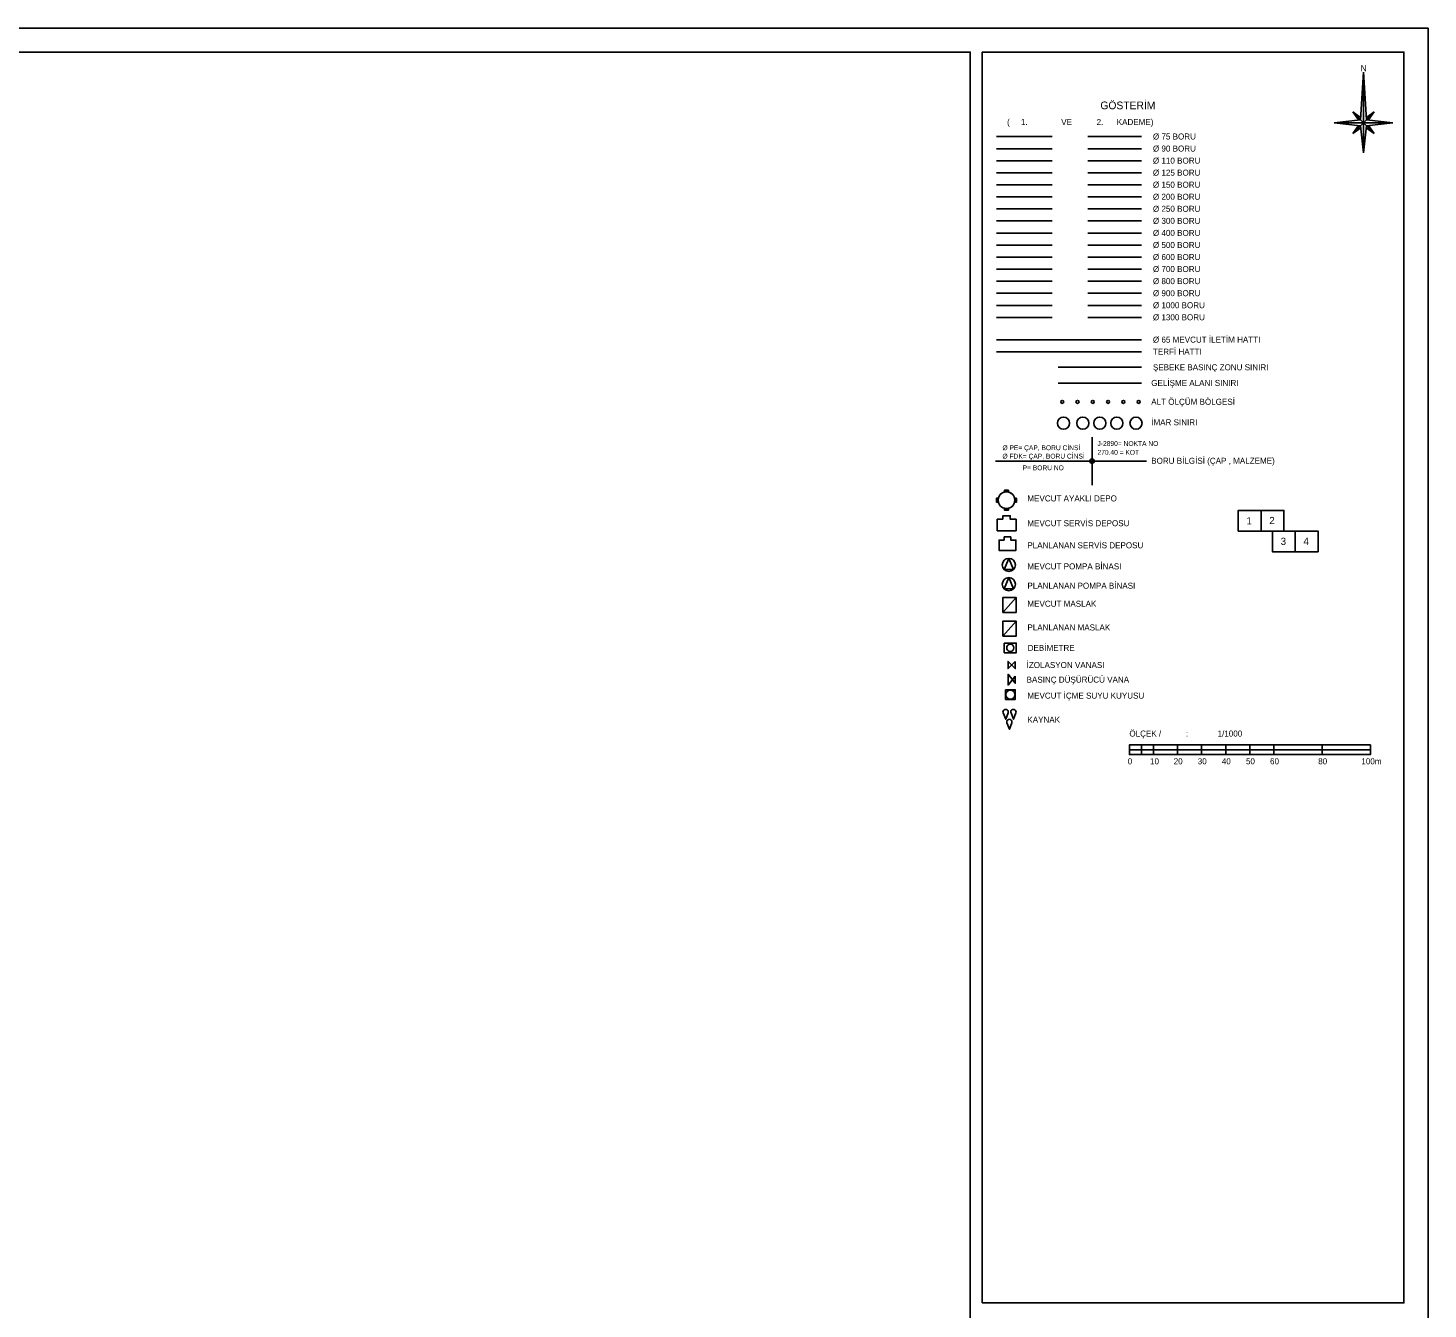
# Model space of a CAD drawing. Extents: x -17 to 1145, y -10 to 821.
# Drawn here: x 564 to 1145, y 290 to 821 of the extents above; entities that cross this region are included whole.
import ezdxf

# ---------------------------------------------------------------- set-up
doc = ezdxf.new("R2010")
doc.units = 0
for name, color, linetype in [('00-SERVIS_DEPO', 7, 'Continuous'), ('00_ALT_BOLGE_SINIRI', 7, 'Continuous'), ('00_GELISME_SINIRI', 7, 'Continuous'), ('00_IMAR SINIRI', 7, 'Continuous'), ('00_KAYNAK', 7, 'Continuous'), ('00_MASLAK', 7, 'Continuous'), ('00_MEVCUT ILETIM HATTI', 7, 'Continuous'), ('00_TERFİ HATTI', 7, 'Continuous'), ('00_TM', 7, 'Continuous'), ('00_VANA', 7, 'Continuous'), ('01_BORU_75', 7, 'Continuous'), ('02_BORU_100', 7, 'Continuous'), ('03_BORU_150', 7, 'Continuous'), ('04_BORU_200', 7, 'Continuous'), ('05_BORU_250', 7, 'Continuous'), ('06_BORU_300', 7, 'Continuous'), ('07_BORU_400', 7, 'Continuous'), ('08_BORU_500', 7, 'Continuous'), ('09_BORU_600', 7, 'Continuous'), ('10_BORU_700', 7, 'Continuous'), ('11_BORU_800', 7, 'Continuous'), ('125_boru', 7, 'Continuous'), ('12_BORU_900', 7, 'Continuous'), ('13_BORU_1000', 7, 'Continuous'), ('14_BORU_1300', 7, 'Continuous'), ('BETON-25', 7, 'Continuous'), ('BETON-60', 7, 'Continuous'), ('Boru Bilgisi', 7, 'Continuous'), ('Default', 7, 'Continuous'), ('Lejand', 7, 'Continuous'), ('Level 50', 7, 'Continuous'), ('Level 51', 7, 'Continuous'), ('Level 52', 7, 'Continuous'), ('PAFTA-20', 7, 'Continuous'), ('ScaleBar-20', 7, 'Continuous'), ('ScaleBar-25', 7, 'Continuous'), ('SEMBOL-10', 7, 'Continuous'), ('SEMBOL-30', 7, 'Continuous'), ('TARAMA-251', 7, 'Continuous'), ('YAZI-25', 7, 'Continuous'), ('YAZI-30', 7, 'Continuous'), ('YAZI-40', 7, 'Continuous'), ('ŞEBEKE BASINC ZON SINIRI', 7, 'Continuous')]:
    doc.layers.add(name, color=color, linetype=linetype)

# ---------------------------------------------------------------- blocks, each defined once
blk = doc.blocks.new('junction_1')
at = {"layer": '00_NODE'}
for start, end in [(45, 225), (45, 225), (225, 45), (225, 45)]:
    blk.add_arc((0, -0.02), 0.914, start, end, dxfattribs=at)
blk = doc.blocks.new('junction_2')
at = {"layer": 'Default'}
blk.add_blockref('junction_1', (0, 0), dxfattribs=at)
blk = doc.blocks.new('A$C32CF5DD8')
at = {"layer": '00_KAYNAK'}
for points in [[(35, 179), (0, 264), (-30, 179)], [(-30, 179), (0, 264), (35, 179)], [(-20, 47), (-54, 132), (-84, 47)], [(-84, 47), (-54, 132), (-20, 47)], [(84, 47), (49, 132), (20, 47)], [(20, 47), (49, 132), (84, 47)]]:
    blk.add_lwpolyline(points, dxfattribs=at)
for centre in [(-52, 35), (-52, 35), (2, 167), (2, 167), (52, 35), (52, 35)]:
    blk.add_arc(centre, 34.6, 159.3514, 20.6486, dxfattribs=at)

msp = doc.modelspace()

# ---------------------------------------------------------------- linework, layer by layer
at = {"layer": '00-SERVIS_DEPO'}
for p, q in [((969.27, 628.45), (969.27, 629.27)), ((969.27, 629.27), (970.87, 629.27)), ((970.87, 628.45), (970.87, 629.27)), ((965.89, 625.88), (966.7, 625.88)), ((965.89, 624.28), (965.89, 625.88)), ((965.89, 624.28), (966.7, 624.28)), ((969.27, 620.9), (969.27, 621.72)), ((970.87, 620.9), (970.87, 621.72)), ((973.44, 625.88), (974.26, 625.88)), ((973.44, 624.28), (974.26, 624.28)), ((974.26, 625.88), (974.26, 624.28)), ((969.27, 620.9), (970.87, 620.9))]:
    msp.add_line(p, q, dxfattribs=at)
for points in [[(970.87, 629.27), (969.27, 629.27), (969.27, 628.45)], [(970.87, 628.45), (970.87, 629.27)], [(966.7, 625.88), (965.89, 625.88), (965.89, 624.28), (966.7, 624.28)], [(969.27, 621.72), (969.27, 620.9), (970.87, 620.9), (970.87, 621.72)], [(974.26, 625.88), (973.44, 625.88)], [(973.44, 624.28), (974.26, 624.28), (974.26, 625.88)], [(968.62, 617.19), (966.24, 617.19), (966.24, 612.38), (974.03, 612.38), (974.03, 617.19), (971.65, 617.19), (971.65, 618.66), (968.62, 618.66), (968.62, 617.19)], [(968.62, 617.19), (966.24, 617.19), (966.24, 612.38), (974.03, 612.38), (974.03, 617.19), (971.65, 617.19), (971.65, 618.66), (968.62, 618.66), (968.62, 617.19)], [(969.11, 608.54), (966.97, 608.54), (966.97, 604.21), (973.98, 604.21), (973.98, 608.54), (971.84, 608.54), (971.84, 609.87), (969.11, 609.87), (969.11, 608.54)]]:
    msp.add_lwpolyline(points, dxfattribs=at)
msp.add_circle((970.07, 625.08), 3.46, dxfattribs=at)
for start, end in [(13.36369, 180), (76.63631, 103.36369), (166.63631, 180), (180, 193.36369), (180, 193.36369), (193.36369, 360), (256.63631, 283.36369), (360, 13.36369), (360, 13.36369), (346.63631, 0)]:
    msp.add_arc((970.07, 625.08), 3.46, start, end, dxfattribs=at)
at = {"layer": '00_ALT_BOLGE_SINIRI'}
for centre, start, end in [((993.19, 665.88), 0, 180), ((993.19, 665.88), 180, 0), ((999.54, 665.88), 0, 180), ((999.54, 665.88), 180, 0), ((1005.88, 665.88), 0, 180), ((1005.88, 665.88), 180, 0), ((1012.23, 665.88), 0, 180), ((1012.23, 665.88), 180, 0), ((1018.58, 665.88), 0, 180), ((1018.58, 665.88), 180, 0), ((1024.93, 665.88), 0, 180), ((1024.93, 665.88), 180, 0)]:
    msp.add_arc(centre, 0.625, start, end, dxfattribs=at)
at = {"layer": '00_GELISME_SINIRI'}
msp.add_line((991.47, 673.69), (1026.14, 673.69), dxfattribs=at)
at = {"layer": '00_IMAR SINIRI'}
for centre in [(993.77, 657.02), (1001.73, 657.02), (1008.79, 657.02), (1015.86, 657.02), (1023.82, 657.02)]:
    msp.add_circle(centre, 2.52, dxfattribs=at)
at = {"layer": '00_MASLAK'}
for p, q in [((974.12, 584.69), (968.54, 578.55)), ((968.54, 578.55), (974.12, 584.69)), ((968.54, 568.71), (974.12, 574.85))]:
    msp.add_line(p, q, dxfattribs=at)
msp.add_lwpolyline([(968.54, 578.55), (974.12, 578.55), (974.12, 584.69)], dxfattribs=at)
for points in [[(968.54, 578.55), (974.12, 578.55), (974.12, 584.69), (968.54, 584.69)], [(968.54, 568.71), (974.12, 568.71), (974.12, 574.85), (968.54, 574.85)]]:
    msp.add_lwpolyline(points, close=True, dxfattribs=at)
at = {"layer": '00_MEVCUT ILETIM HATTI'}
msp.add_line((965.89, 691.65), (1026.14, 691.65), dxfattribs=at)
at = {"layer": '00_TERFİ HATTI'}
msp.add_line((965.89, 686.65), (1026.14, 686.65), dxfattribs=at)
at = {"layer": '00_TM'}
for points in [[(972.98, 596.27), (971.05, 600.95), (969.12, 596.31), (972.98, 596.27)], [(972.98, 596.27), (971.05, 600.95), (969.12, 596.31), (972.98, 596.27)], [(972.98, 588.26), (971.05, 592.95), (969.12, 588.3), (972.98, 588.26)]]:
    msp.add_lwpolyline(points, dxfattribs=at)
for centre in [(971.07, 598.22), (971.07, 590.21)]:
    msp.add_circle(centre, 2.73, dxfattribs=at)
at = {"layer": '00_VANA'}
for points in [[(973.71, 558.19), (970.71, 555.19), (970.71, 558.19), (973.71, 555.19), (973.71, 558.19)], [(973.71, 552.13), (970.71, 548.38), (970.71, 552.88), (973.71, 549.13), (973.71, 552.13)]]:
    msp.add_lwpolyline(points, dxfattribs=at)
at = {"layer": '01_BORU_75'}
for p, q in [((965.89, 775.93), (989.08, 775.93)), ((1003.79, 775.93), (1026.14, 775.93))]:
    msp.add_line(p, q, dxfattribs=at)
at = {"layer": '02_BORU_100'}
for p, q in [((965.89, 770.93), (989.08, 770.93)), ((1003.79, 770.93), (1026.14, 770.93)), ((965.89, 765.93), (989.08, 765.93)), ((1003.79, 765.93), (1026.14, 765.93))]:
    msp.add_line(p, q, dxfattribs=at)
at = {"layer": '03_BORU_150'}
for p, q in [((965.89, 755.93), (989.08, 755.93)), ((1003.79, 755.93), (1026.14, 755.93))]:
    msp.add_line(p, q, dxfattribs=at)
at = {"layer": '04_BORU_200'}
for p, q in [((965.89, 750.93), (989.08, 750.93)), ((1003.79, 750.93), (1026.14, 750.93))]:
    msp.add_line(p, q, dxfattribs=at)
at = {"layer": '05_BORU_250'}
for p, q in [((965.89, 745.93), (989.08, 745.93)), ((1003.79, 745.93), (1026.14, 745.93))]:
    msp.add_line(p, q, dxfattribs=at)
at = {"layer": '06_BORU_300'}
for p, q in [((965.89, 740.93), (989.08, 740.93)), ((1003.79, 740.93), (1026.14, 740.93))]:
    msp.add_line(p, q, dxfattribs=at)
at = {"layer": '07_BORU_400'}
for p, q in [((965.89, 735.93), (989.08, 735.93)), ((1003.79, 735.93), (1026.14, 735.93))]:
    msp.add_line(p, q, dxfattribs=at)
at = {"layer": '08_BORU_500'}
for p, q in [((965.89, 730.93), (989.08, 730.93)), ((1003.79, 730.93), (1026.14, 730.93))]:
    msp.add_line(p, q, dxfattribs=at)
at = {"layer": '09_BORU_600'}
for p, q in [((965.89, 725.93), (989.08, 725.93)), ((1003.79, 725.93), (1026.14, 725.93))]:
    msp.add_line(p, q, dxfattribs=at)
at = {"layer": '10_BORU_700'}
for p, q in [((965.89, 720.93), (989.08, 720.93)), ((1003.79, 720.93), (1026.14, 720.93))]:
    msp.add_line(p, q, dxfattribs=at)
at = {"layer": '11_BORU_800'}
for p, q in [((965.89, 715.93), (989.08, 715.93)), ((1003.79, 715.93), (1026.14, 715.93))]:
    msp.add_line(p, q, dxfattribs=at)
at = {"layer": '125_boru'}
for p, q in [((965.89, 760.93), (989.08, 760.93)), ((1003.79, 760.93), (1026.14, 760.93))]:
    msp.add_line(p, q, dxfattribs=at)
at = {"layer": '12_BORU_900'}
for p, q in [((965.89, 710.93), (989.08, 710.93)), ((1003.79, 710.93), (1026.14, 710.93))]:
    msp.add_line(p, q, dxfattribs=at)
at = {"layer": '13_BORU_1000'}
for p, q in [((965.89, 705.93), (989.08, 705.93)), ((1003.79, 705.93), (1026.14, 705.93))]:
    msp.add_line(p, q, dxfattribs=at)
at = {"layer": '14_BORU_1300'}
for p, q in [((965.89, 700.93), (989.08, 700.93)), ((1003.79, 700.93), (1026.14, 700.93))]:
    msp.add_line(p, q, dxfattribs=at)
at = {"layer": 'BETON-25'}
msp.add_lwpolyline([(969.15, 565.81), (974.15, 565.81), (974.15, 561.81), (969.15, 561.81)], close=True, dxfattribs=at)
msp.add_circle((971.65, 563.81), 1.5, dxfattribs=at)
at = {"layer": 'BETON-60'}
for p, q in [((1005.58, 641.3), (1005.58, 651.3)), ((965.57, 641.3), (1005.58, 641.3)), ((1005.58, 631.3), (1005.58, 641.3)), ((1028.23, 641.3), (1005.58, 641.3))]:
    msp.add_line(p, q, dxfattribs=at)
at = {"layer": 'Lejand'}
for p, q in [((1118.22, 802.67), (1116.97, 782.96)), ((1118.22, 802.67), (1119.47, 782.96)), ((1118.22, 802.67), (1118.22, 769.23)), ((1113.84, 786.17), (1117.03, 783.81)), ((1116.17, 782.87), (1113.84, 786.17)), ((1113.84, 786.17), (1118.22, 781.68)), ((1122.6, 786.17), (1118.22, 781.68)), ((1122.6, 786.17), (1119.42, 783.81)), ((1120.27, 782.87), (1122.6, 786.17)), ((1106.03, 781.68), (1116.97, 782.96)), ((1118.22, 781.68), (1106.03, 781.68)), ((1106.03, 781.68), (1116.97, 780.4)), ((1113.84, 777.19), (1118.22, 781.68)), ((1116.17, 780.49), (1113.84, 777.19)), ((1113.84, 777.19), (1117.07, 779.58)), ((1116.97, 780.4), (1118.22, 769.23)), ((1122.6, 777.19), (1118.22, 781.68)), ((1118.22, 781.68), (1130.41, 781.68)), ((1119.47, 780.4), (1118.22, 769.23)), ((1122.6, 777.19), (1119.38, 779.58)), ((1130.35, 781.68), (1119.47, 782.96)), ((1130.35, 781.68), (1119.47, 780.4)), ((1120.27, 780.49), (1122.6, 777.19))]:
    msp.add_line(p, q, dxfattribs=at)
at = {"layer": 'Level 50'}
msp.add_lwpolyline([(-7, 0), (955, 0), (955, 811), (-7, 811)], close=True, dxfattribs=at)
at = {"layer": 'Level 51'}
msp.add_lwpolyline([(-17, -10), (1145, -10), (1145, 821), (-17, 821)], close=True, dxfattribs=at)
at = {"layer": 'Level 52'}
msp.add_lwpolyline([(960, 292), (1135, 292), (1135, 811), (960, 811)], close=True, dxfattribs=at)
at = {"layer": 'PAFTA-20'}
for points in [[(1075.74, 612.24), (1066.28, 612.24), (1066.28, 620.86), (1075.74, 620.86)], [(1085.21, 612.24), (1075.74, 612.24), (1075.74, 620.86), (1085.21, 620.86)], [(1089.94, 603.61), (1080.47, 603.61), (1080.47, 612.24), (1089.94, 612.24)], [(1099.4, 603.61), (1089.94, 603.61), (1089.94, 612.24), (1099.4, 612.24)]]:
    msp.add_lwpolyline(points, close=True, dxfattribs=at)
at = {"layer": 'ScaleBar-20'}
for p, q in [((1026.07, 523.51), (1026.07, 519.51)), ((1031.07, 523.51), (1031.07, 519.51)), ((1041.07, 523.51), (1041.07, 519.51)), ((1051.07, 523.51), (1051.07, 519.51)), ((1061.07, 523.51), (1061.07, 519.51)), ((1071.07, 523.51), (1071.07, 519.51)), ((1081.07, 523.51), (1081.07, 519.51)), ((1101.07, 523.51), (1101.07, 519.51)), ((1021.07, 521.51), (1121.07, 521.51))]:
    msp.add_line(p, q, dxfattribs=at)
for points in [[(1021.07, 523.51), (1021.07, 521.51), (1026.07, 521.51), (1026.07, 523.51)], [(1031.07, 523.51), (1031.07, 521.51), (1041.07, 521.51), (1041.07, 523.51)], [(1051.07, 523.51), (1051.07, 521.51), (1061.07, 521.51), (1061.07, 523.51)], [(1071.07, 523.51), (1071.07, 521.51), (1081.07, 521.51), (1081.07, 523.51)], [(1101.07, 523.51), (1101.07, 521.51), (1121.07, 521.51), (1121.07, 523.51)], [(1026.07, 521.51), (1026.07, 519.51), (1031.07, 519.51), (1031.07, 521.51)], [(1041.07, 521.51), (1041.07, 519.51), (1051.07, 519.51), (1051.07, 521.51)], [(1061.07, 521.51), (1061.07, 519.51), (1071.07, 519.51), (1071.07, 521.51)], [(1081.07, 521.51), (1081.07, 519.51), (1101.07, 519.51), (1101.07, 521.51)]]:
    msp.add_lwpolyline(points, close=True, dxfattribs=at)
at = {"layer": 'ScaleBar-25'}
msp.add_lwpolyline([(1121.07, 523.51), (1021.07, 523.51), (1021.07, 519.51), (1121.07, 519.51)], close=True, dxfattribs=at)
at = {"layer": 'SEMBOL-10'}
msp.add_circle((971.71, 544.42), 1.9, dxfattribs=at)
msp.add_circle((971.71, 544.42), 1.9, dxfattribs=at)
at = {"layer": 'SEMBOL-30'}
msp.add_lwpolyline([(969.71, 546.42), (969.71, 542.42), (973.71, 542.42), (973.71, 546.42)], close=True, dxfattribs=at)
at = {"layer": 'TARAMA-251'}
msp.add_lwpolyline([(1075.74, 620.86), (1066.28, 620.86), (1066.28, 612.24), (1075.74, 612.24), (1075.74, 620.86)], dxfattribs=at)
at = {"layer": 'ŞEBEKE BASINC ZON SINIRI'}
msp.add_line((991.47, 680.23), (1026.14, 680.23), dxfattribs=at)

# ---------------------------------------------------------------- block references
at = {"layer": 'Default'}
msp.add_blockref('junction_2', (1005.58, 641.3), dxfattribs=at)
at = {"layer": 'Default', "xscale": 0.03125, "yscale": 0.03125, "rotation": 180}
msp.add_blockref('A$C32CF5DD8', (971.33, 538.32), dxfattribs=at)

# ---------------------------------------------------------------- texts
at = {"layer": 'Boru Bilgisi'}
for s, height, p in [('%%C PE= ÇAP, BORU CİNSİ', 2.0003, (968.4, 645.84)), ('J-2890= NOKTA NO', 2.0003, (1007.84, 647.59)), ('270.40 = KOT', 2.0003, (1007.84, 643.94)), ('%%C FDK= ÇAP, BORU CİNSİ', 2.0003, (968.4, 642.35)), ('P= BORU NO', 2, (976.76, 637.52))]:
    msp.add_text(s, height=height, dxfattribs=at).set_placement(p)
at = {"layer": 'Lejand'}
msp.add_text('N', height=2.56, dxfattribs=at).set_placement((1117.02, 803.06))
at = {"layer": 'ScaleBar-25'}
for s, p in [('ÖLÇEK /           :', (1021.07, 527.01)), ('  1/1000', (1055.83, 527.01)), ('0', (1020.4, 515.51)), ('10', (1029.64, 515.51)), ('20', (1039.45, 515.51)), ('30', (1049.45, 515.51)), ('40', (1059.45, 515.51)), ('50', (1069.45, 515.51)), ('60', (1079.45, 515.51)), ('80', (1099.45, 515.51)), ('100m', (1117.36, 515.51))]:
    msp.add_text(s, height=2.5, dxfattribs=at).set_placement(p)
at = {"layer": 'YAZI-25'}
for s, p in [('(     1.               VE           2.      KADEME)', (970.31, 780.74)), ('%%C 75 BORU', (1030.85, 774.73)), ('%%C 90 BORU', (1030.85, 769.73)), ('%%C 110 BORU', (1030.85, 764.73)), ('%%C 125 BORU', (1030.85, 759.73)), ('%%C 150 BORU', (1030.85, 754.73)), ('%%C 200 BORU', (1030.85, 749.73)), ('%%C 250 BORU', (1030.85, 744.73)), ('%%C 300 BORU', (1030.85, 739.73)), ('%%C 400 BORU', (1030.85, 734.73)), ('%%C 500 BORU', (1030.85, 729.73)), ('%%C 600 BORU', (1030.85, 724.73)), ('%%C 700 BORU', (1030.85, 719.73)), ('%%C 800 BORU', (1030.85, 714.73)), ('%%C 900 BORU', (1030.85, 709.73)), ('%%C 1000 BORU', (1030.85, 704.73)), ('%%C 1300 BORU', (1030.85, 699.73)), ('%%C 65 MEVCUT İLETİM HATTI', (1030.85, 690.45)), ('TERFİ HATTI', (1030.85, 685.45)), ('ŞEBEKE BASINÇ ZONU SINIRI', (1030.85, 678.98)), ('GELİŞME ALANI SINIRI', (1030.14, 672.49)), ('ALT ÖLÇÜM BÖLGESİ', (1030.14, 664.66)), ('İMAR SINIRI', (1030.14, 656.17)), ('BORU BİLGİSİ (ÇAP , MALZEME)', (1030.14, 640.18)), ('MEVCUT AYAKLI DEPO', (978.74, 624.57)), ('MEVCUT SERVİS DEPOSU', (978.74, 614.29)), ('PLANLANAN SERVİS DEPOSU', (978.74, 605.13)), ('MEVCUT POMPA BİNASI', (978.76, 596.37)), ('PLANLANAN POMPA BİNASI', (978.76, 588.36)), ('MEVCUT MASLAK', (978.76, 580.87)), ('PLANLANAN MASLAK', (978.76, 571.04)), ('DEBİMETRE', (978.86, 562.56)), ('İZOLASYON VANASI', (978.42, 555.44)), ('BASINÇ DÜŞÜRÜCÜ VANA', (978.42, 549.38)), ('MEVCUT İÇME SUYU KUYUSU', (978.76, 542.75)), ('KAYNAK', (978.74, 532.76))]:
    msp.add_text(s, height=2.5, dxfattribs=at).set_placement(p)
at = {"layer": 'YAZI-30'}
for s, p in [('1', (1069.67, 615.04)), ('2', (1079.14, 615.15)), ('3', (1083.87, 606.53)), ('4', (1093.33, 606.53))]:
    msp.add_text(s, height=3, dxfattribs=at).set_placement(p)
at = {"layer": 'YAZI-40'}
msp.add_text(' GÖSTERİM ', height=3.2, dxfattribs=at).set_placement((1007.85, 787.29))

doc.saveas('drawing.dxf')
